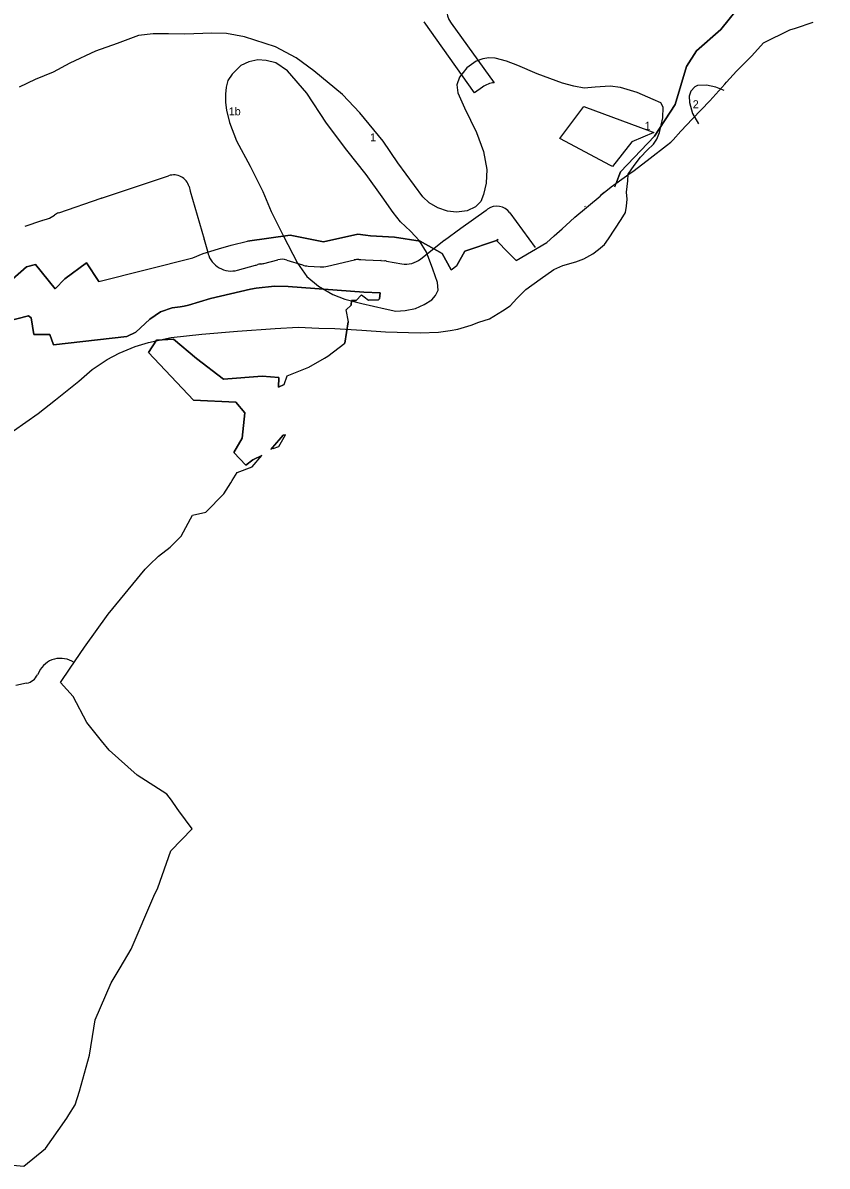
# Model space of a CAD drawing. Extents: x -445049 to -430649, y -1142304 to -1129816.
# Drawn here: x -443678 to -442673, y -1134562 to -1133134 of the extents above; entities that cross this region are included whole.
import ezdxf

# ---------------------------------------------------------------- set-up
doc = ezdxf.new("R2010")
doc.units = 0
for name, color, linetype in [('Vrstva 23', 7, 'Continuous'), ('Vrstva 51', 7, 'Continuous'), ('Vrstva 7', 7, 'Continuous'), ('Vrstva 8', 7, 'Continuous'), ('Vrstva 9', 7, 'Continuous')]:
    doc.layers.add(name, color=color, linetype=linetype)

msp = doc.modelspace()

# ---------------------------------------------------------------- linework, layer by layer
at = {"layer": 'Vrstva 23'}
for p, q in [((-443143, -1133133.8), (-443089, -1133208.5)), ((-443508.6, -1133328.8), (-443496, -1133324.6)), ((-443580.1, -1133352.5), (-443508.6, -1133328.8)), ((-443470.4, -1133338.2), (-443468.9, -1133343.7)), ((-443633.3, -1133370.9), (-443580.4, -1133352.6)), ((-443468.9, -1133343.8), (-443451.7, -1133404)), ((-443098.9, -1133367.5), (-443097.4, -1133366.4)), ((-443675.3, -1133387.8), (-443654.3, -1133380.7)), ((-443654.3, -1133380.7), (-443647.3, -1133378.3)), ((-443069.5, -1133370.9), (-443037.8, -1133414.4)), ((-443451.6, -1133404.2), (-443446.8, -1133421.6)), ((-443180.9, -1133428.5), (-443152.1, -1133405.6)), ((-443409.9, -1133442.6), (-443387.3, -1133436.4)), ((-443376.9, -1133434.1), (-443359.4, -1133429.6)), ((-443348.4, -1133429.9), (-443328.7, -1133436.1)), ((-443321.6, -1133437.4), (-443306.4, -1133438.4)), ((-443297.6, -1133437.7), (-443263.9, -1133429.8)), ((-443258.4, -1133429.3), (-443255.8, -1133429.4)), ((-443255.7, -1133429.4), (-443250, -1133429.7)), ((-443250, -1133429.7), (-443230.8, -1133430.7)), ((-443230.6, -1133430.7), (-443225.9, -1133431)), ((-443223.8, -1133431.2), (-443204.7, -1133434.5)), ((-443658, -1133944.3), (-443659.9, -1133948.1)), ((-443673.5, -1133958.7), (-443687, -1133961.7))]:
    msp.add_line(p, q, dxfattribs=at)
for points in [[(-443103.8, -1133213.9), (-443113.6, -1133220.9), (-443176.6, -1133132.3)], [(-443151.3, -1133405), (-443130.7, -1133390.3), (-443099, -1133367.6)]]:
    msp.add_lwpolyline(points, dxfattribs=at)
for centre, radius, start, end in [((-443118.7, -1133116.3), 30, 138.9795, 215.8663), ((-443086.4, -1133238.3), 30, 95.036, 125.4139), ((-443489.7, -1133343.6), 20, 15.6761, 108.4331), ((-443518.1, -1133300.3), 30, 288.3161, 288.4331), ((-443573.8, -1133371.5), 20, 108.3161, 109.0994), ((-443440, -1133335.6), 30, 195.6761, 195.9557), ((-443116.4, -1133343.2), 30, 305.6204, 305.8262), ((-443085.7, -1133382.7), 20, 36.0604, 125.8262), ((-443663.9, -1133352.3), 30, 288.6899, 288.7113), ((-443656.9, -1133349.9), 30, 288.7113, 307.1241), ((-443626.7, -1133389.8), 20, 109.0994, 127.1241), ((-443470.9, -1133409.5), 20, 15.2701, 15.9557), ((-443139.6, -1133421.3), 20, 125.615, 128.3723), ((-443417.9, -1133413.7), 30, 195.2701, 285.3949), ((-443395.3, -1133407.5), 30, 285.3949, 289.0956), ((-443378.9, -1133454.7), 20, 96.1778, 109.0956), ((-443384.3, -1133405), 30, 276.1778, 284.3857), ((-443354.4, -1133449), 20, 72.539, 104.3857), ((-443319.7, -1133407.5), 30, 252.539, 266.3185), ((-443304.4, -1133408.5), 30, 266.3185, 283.2162), ((-443259.4, -1133449.3), 20, 87.2484, 103.2162), ((-443256.8, -1133449.4), 20, 87.0859, 87.2484), ((-443248.5, -1133399.7), 30, 267.0859, 267.1026), ((-443231.8, -1133450.6), 20, 86.42, 87.1026), ((-443227.2, -1133450.9), 20, 80.1563, 86.42), ((-443199.6, -1133405), 30, 260.1563, 308.3723), ((-443631.1, -1133957.6), 30, 55.8038, 153.678), ((-443677.8, -1133939.2), 20, 282.5288, 333.678)]:
    msp.add_arc(centre, radius, start, end, dxfattribs=at)
at = {"layer": 'Vrstva 51'}
for points in [[(-442922.1, -1133330.9), (-442921.5, -1133322.5), (-442914.1, -1133311.8), (-442906.4, -1133301.6), (-442897.7, -1133292.6), (-442889.8, -1133285.1), (-442885.8, -1133278.9), (-442882.5, -1133270.6), (-442878.4, -1133252.1), (-442877.8, -1133239), (-442880.9, -1133233.7), (-442890.2, -1133229.2), (-442910.4, -1133220.7), (-442931.1, -1133214.2), (-442944.1, -1133212.8), (-442962.7, -1133214.1), (-442976.7, -1133215), (-442989.6, -1133212.5), (-443003.6, -1133209.1), (-443035.5, -1133197.4), (-443059.4, -1133186.8), (-443073.6, -1133181.5), (-443088, -1133177.7), (-443096, -1133177.1), (-443103.5, -1133178.5), (-443111.8, -1133181.3), (-443123.2, -1133189.7), (-443132.6, -1133201.3), (-443135.6, -1133211.1), (-443134.4, -1133220.9), (-443126.2, -1133239.6), (-443111.2, -1133270.4), (-443102.5, -1133294.2), (-443098.5, -1133316.9), (-443099.3, -1133333.8), (-443102.4, -1133348.2), (-443105.7, -1133356.8), (-443112.4, -1133363.6), (-443122.8, -1133368.6), (-443136, -1133370.3), (-443147.5, -1133368.7), (-443159.5, -1133364.7), (-443170.2, -1133358.5), (-443178.1, -1133351), (-443209.6, -1133308.5), (-443227.7, -1133281.3), (-443257, -1133246), (-443278.8, -1133223.1), (-443314.4, -1133193.4), (-443336.7, -1133177.1), (-443362.6, -1133163.6), (-443401, -1133151.1), (-443423.8, -1133146.7), (-443441.9, -1133146.4), (-443475.6, -1133147.8), (-443496, -1133147.4), (-443515.4, -1133147.2), (-443533.6, -1133149.5), (-443560.5, -1133159.4), (-443587.4, -1133168.8), (-443619.3, -1133184), (-443640.2, -1133195.2), (-443663, -1133204.5), (-443682.9, -1133214)], [(-442801.5, -1133218.1), (-442811.9, -1133213.9), (-442823.7, -1133211.4), (-442834.9, -1133211.8), (-442838.5, -1133213.4), (-442843.5, -1133218.8), (-442845.6, -1133225.2), (-442845, -1133233), (-442841.4, -1133246.7), (-442833.9, -1133259.6)], [(-443254.6, -1133517.4), (-443224.9, -1133519.7), (-443181.8, -1133520.9), (-443158.6, -1133520), (-443144, -1133518), (-443134.6, -1133516.2), (-443117.8, -1133511.5), (-443108.5, -1133507.4), (-443095.1, -1133503.4), (-443078.6, -1133493.4), (-443069.2, -1133487.2), (-443060.8, -1133477.8), (-443049.6, -1133466.7), (-443031.6, -1133453.8), (-443014.5, -1133441.9), (-443003.3, -1133436.6), (-442987.2, -1133432), (-442976.9, -1133428.6), (-442965.6, -1133422.1), (-442958.7, -1133416.8), (-442951.3, -1133410.5), (-442946.1, -1133403.5), (-442930.4, -1133379.3), (-442925.1, -1133370.4), (-442923.8, -1133362.8), (-442923.1, -1133354), (-442923.6, -1133345.1), (-442922.1, -1133330.9)], [(-443690, -1133643.2), (-443659.1, -1133621.8), (-443637.2, -1133604.4), (-443608.2, -1133581.4), (-443591.7, -1133566.7), (-443572.7, -1133554.2), (-443557.7, -1133546.1), (-443538, -1133537.8), (-443521.2, -1133532.9), (-443493, -1133526.8), (-443454.6, -1133522.5), (-443410, -1133518.6), (-443363, -1133515.5), (-443334.1, -1133514), (-443308.4, -1133514.9), (-443288.4, -1133515.4), (-443254.6, -1133517.4)]]:
    msp.add_lwpolyline(points, dxfattribs=at)
msp.add_lwpolyline([(-443173.7, -1133420), (-443182.3, -1133405.8), (-443193.7, -1133393.8), (-443206.3, -1133382), (-443215.5, -1133370.5), (-443229, -1133351), (-443249.3, -1133322.9), (-443273.2, -1133292.5), (-443298.5, -1133259), (-443323.4, -1133221.3), (-443347.5, -1133193.6), (-443362.2, -1133183.7), (-443374.3, -1133180.5), (-443384.7, -1133179.7), (-443395.7, -1133182.3), (-443405.6, -1133187), (-443416.5, -1133197.7), (-443422.1, -1133205.8), (-443423.9, -1133214.1), (-443424.9, -1133222.5), (-443424.9, -1133232.9), (-443423.7, -1133242.7), (-443419.9, -1133258), (-443411.2, -1133281), (-443393.9, -1133312.8), (-443378.2, -1133344.4), (-443367.7, -1133369.1), (-443353, -1133399.1), (-443335.1, -1133434), (-443323.3, -1133450.4), (-443308.8, -1133462.6), (-443290.6, -1133472.9), (-443275.7, -1133479), (-443254.5, -1133484.1), (-443225.3, -1133490.9), (-443212, -1133493.8), (-443200.4, -1133493.1), (-443187.5, -1133490.3), (-443176.7, -1133485.3), (-443167, -1133479.8), (-443162.4, -1133474.4), (-443159.2, -1133467.7), (-443160, -1133458), (-443165.7, -1133441.4)], close=True, dxfattribs=at)
at = {"layer": 'Vrstva 7'}
for points in [[(-443712.5, -1133472.1), (-443673.7, -1133438.5), (-443662.5, -1133435.5), (-443638, -1133466.1), (-443625.9, -1133453.6), (-443598.5, -1133433.4), (-443583.4, -1133456.8), (-443465.7, -1133427.3), (-443452.8, -1133421.7), (-443433.7, -1133416), (-443418, -1133411.2), (-443397.6, -1133406.4), (-443344.3, -1133398.7), (-443302.5, -1133407.1), (-443259.6, -1133397.6), (-443249.9, -1133398.8), (-443243.6, -1133399.5), (-443213.8, -1133401.2), (-443181.5, -1133406.4), (-443154.3, -1133421.9), (-443143, -1133442.1), (-443135.6, -1133436.7), (-443125.8, -1133419), (-443086.4, -1133405.7), (-443084.2, -1133404.2), (-443086.4, -1133405.7), (-443071.4, -1133421), (-443061.5, -1133430.7), (-443023.3, -1133407.9), (-443019.2, -1133404.3), (-443014, -1133399.8), (-443004.2, -1133390.8), (-442994.3, -1133381.9), (-442988.4, -1133376.5), (-442956.8, -1133350), (-442951.6, -1133345.7), (-442943, -1133338.4), (-442923.8, -1133324.8), (-442921.9, -1133323.4), (-442914.2, -1133317.9), (-442894.3, -1133302.8), (-442873.8, -1133286.9), (-442868.2, -1133282.6), (-442865.4, -1133279.6), (-442855.8, -1133269.1), (-442841.2, -1133253.6), (-442819.5, -1133231), (-442812, -1133222.7), (-442800.9, -1133210.2), (-442798.6, -1133207.7), (-442786.1, -1133194), (-442767.1, -1133174.9), (-442752.3, -1133158.7), (-442719.4, -1133142.5), (-442712.7, -1133140.2), (-442690.5, -1133132.6)], [(-442951.6, -1133345.7), (-442943, -1133338.4), (-442923.8, -1133324.8), (-442921.9, -1133323.4), (-442914.2, -1133317.9), (-442894.3, -1133302.8), (-442873.8, -1133286.9), (-442868.2, -1133282.6), (-442865.4, -1133279.6), (-442855.8, -1133269.1), (-442841.2, -1133253.6), (-442819.5, -1133231), (-442812, -1133222.7), (-442800.9, -1133210.2), (-442798.6, -1133207.7), (-442786.1, -1133194), (-442767.1, -1133174.9), (-442752.3, -1133158.7), (-442719.4, -1133142.5), (-442712.7, -1133140.2), (-442690.5, -1133132.6)], [(-442917.1, -1133282.1), (-442941.2, -1133313.1), (-442943.6, -1133311.8), (-443006.9, -1133278), (-442977.1, -1133238.1), (-442894.9, -1133268.6), (-442889.4, -1133270.7), (-442917.1, -1133282.1)], [(-442894.9, -1133268.6), (-442889.4, -1133270.7), (-442917.1, -1133282.1), (-442941.2, -1133313.1), (-442943.6, -1133311.8), (-443006.9, -1133278), (-442977.1, -1133238.1), (-442894.9, -1133268.6)], [(-443006.9, -1133278), (-442977.1, -1133238.1), (-442894.9, -1133268.6), (-442889.4, -1133270.7), (-442917.1, -1133282.1), (-442941.2, -1133313.1), (-442943.6, -1133311.8), (-443006.9, -1133278)], [(-443006.9, -1133278), (-442977.1, -1133238.1), (-442894.9, -1133268.6), (-442889.4, -1133270.7), (-442917.1, -1133282.1), (-442941.2, -1133313.1), (-442943.6, -1133311.8), (-443006.9, -1133278)], [(-443712.5, -1133472.1), (-443673.7, -1133438.5), (-443662.5, -1133435.5), (-443638, -1133466.1), (-443625.9, -1133453.6), (-443598.5, -1133433.4), (-443583.4, -1133456.8), (-443465.7, -1133427.3), (-443452.8, -1133421.7), (-443433.7, -1133416), (-443418, -1133411.2), (-443397.6, -1133406.4), (-443344.3, -1133398.7), (-443302.5, -1133407.1), (-443259.6, -1133397.6), (-443249.9, -1133398.8), (-443243.6, -1133399.5), (-443213.8, -1133401.2), (-443181.5, -1133406.4), (-443154.3, -1133421.9), (-443143, -1133442.1), (-443135.6, -1133436.7), (-443125.8, -1133419), (-443086.4, -1133405.7), (-443084.2, -1133404.2), (-443086.4, -1133405.7), (-443071.4, -1133421), (-443061.5, -1133430.7), (-443023.3, -1133407.9), (-443019.2, -1133404.3), (-443014, -1133399.8), (-443004.2, -1133390.8), (-442994.3, -1133381.9), (-442988.4, -1133376.5), (-442956.8, -1133350)], [(-442951.6, -1133345.7), (-442956.5, -1133349.8)], [(-442975.2, -1133362.9), (-442976.1, -1133363.5)], [(-443712.5, -1133472.1), (-443673.7, -1133438.5), (-443662.5, -1133435.5), (-443638, -1133466.1), (-443625.9, -1133453.6), (-443598.5, -1133433.4), (-443583.4, -1133456.8), (-443465.7, -1133427.3), (-443452.8, -1133421.7), (-443433.7, -1133416), (-443418, -1133411.2), (-443397.6, -1133406.4), (-443344.3, -1133398.7), (-443302.5, -1133407.1), (-443259.6, -1133397.6), (-443249.9, -1133398.8), (-443243.6, -1133399.5), (-443213.8, -1133401.2), (-443181.5, -1133406.4), (-443154.3, -1133421.9), (-443143, -1133442.1), (-443135.6, -1133436.7), (-443125.8, -1133419), (-443086.4, -1133405.7), (-443084.2, -1133404.2)], [(-443583.4, -1133456.8), (-443465.7, -1133427.3), (-443452.8, -1133421.7), (-443433.7, -1133416), (-443418, -1133411.2), (-443397.6, -1133406.4)], [(-443143, -1133442.1), (-443154.3, -1133421.9), (-443181.5, -1133406.4), (-443213.8, -1133401.2), (-443243.6, -1133399.5), (-443249.9, -1133398.8), (-443259.6, -1133397.6), (-443302.5, -1133407.1), (-443344.3, -1133398.7), (-443397.6, -1133406.4)], [(-443084.2, -1133404.2), (-443086.4, -1133405.7), (-443125.8, -1133419), (-443135.6, -1133436.8)], [(-443583.4, -1133456.8), (-443598.5, -1133433.4), (-443625.9, -1133453.6), (-443638, -1133466.1), (-443662.5, -1133435.5), (-443673.7, -1133438.5), (-443712.5, -1133472.1), (-443735.9, -1133482.8), (-443718.8, -1133511.9), (-443671.1, -1133499.8), (-443668, -1133502.3), (-443664.3, -1133522.9), (-443644.5, -1133522.8), (-443640, -1133535.8), (-443548.3, -1133525.6)], [(-443737, -1134556.5), (-443676.9, -1134562.1), (-443649.8, -1134540.2), (-443633.9, -1134517.4), (-443623.1, -1134502.1), (-443620.7, -1134498.1), (-443613, -1134485.6), (-443607.6, -1134468.5), (-443594.8, -1134423.4), (-443589.3, -1134389.5), (-443587.7, -1134379.4), (-443567.8, -1134333.2), (-443556.7, -1134314.5), (-443542.7, -1134290.9), (-443514.7, -1134224.7), (-443509.6, -1134214.4), (-443493.3, -1134168), (-443466.4, -1134140.8), (-443483.2, -1134118.2), (-443485.3, -1134115.3), (-443492.5, -1134104.8), (-443498.3, -1134097.4), (-443535.5, -1134073.4), (-443570.5, -1134042.3), (-443579.9, -1134030.6), (-443598.2, -1134007.9), (-443615.3, -1133975.2), (-443631.1, -1133957.6), (-443619, -1133939.8), (-443601.3, -1133913.7), (-443571.4, -1133872.6), (-443525.4, -1133816.1), (-443519.9, -1133810.9), (-443508.5, -1133799.8), (-443494.1, -1133788.5), (-443480.2, -1133775), (-443468.6, -1133753.3), (-443466.2, -1133748.9), (-443449.4, -1133745.1), (-443427.1, -1133722.1), (-443418.4, -1133708.5), (-443416.5, -1133705.4), (-443410.3, -1133695.4), (-443391.7, -1133688.2), (-443379.6, -1133674.2), (-443390.8, -1133679.5), (-443399.5, -1133686.1), (-443414.5, -1133670.6), (-443404, -1133652.5), (-443400.8, -1133620.8), (-443412.2, -1133607.4), (-443465, -1133605), (-443521.1, -1133545.4), (-443511.2, -1133529.9), (-443489.9, -1133528.6), (-443461.2, -1133553), (-443427.5, -1133578.8), (-443379, -1133575.1), (-443358.3, -1133576.6), (-443358.5, -1133588.7), (-443351.8, -1133585.6), (-443347.8, -1133574.5), (-443320.6, -1133563.8), (-443301.3, -1133552.4), (-443297.2, -1133549.9), (-443275.6, -1133533.6), (-443271.6, -1133507.3), (-443271.3, -1133507.1), (-443274.1, -1133492.3), (-443267.8, -1133486.2), (-443267.3, -1133480.4), (-443261.8, -1133480.3), (-443254.8, -1133473.4), (-443251.5, -1133475.9), (-443246.4, -1133479.9), (-443233.7, -1133479.6), (-443232.3, -1133478.6), (-443231.6, -1133471.1), (-443252.2, -1133470.2), (-443346.6, -1133462.9), (-443363.8, -1133462.4), (-443386.4, -1133465.1), (-443393.6, -1133466.3), (-443443.7, -1133477.9), (-443471.1, -1133486.5), (-443476.7, -1133487.4), (-443481.5, -1133488.2), (-443491.5, -1133489.8), (-443506.2, -1133494.5), (-443519.4, -1133503.8), (-443536.8, -1133520), (-443548.3, -1133525.6), (-443640, -1133535.8), (-443644.5, -1133522.8), (-443664.3, -1133522.9), (-443668, -1133502.3), (-443671.1, -1133499.8), (-443718.8, -1133511.9)], [(-443737, -1134556.5), (-443676.9, -1134562.1), (-443649.8, -1134540.2), (-443633.9, -1134517.4), (-443623.1, -1134502.1), (-443620.7, -1134498.1), (-443613, -1134485.6), (-443607.6, -1134468.5), (-443594.8, -1134423.4), (-443589.3, -1134389.5), (-443587.7, -1134379.4), (-443567.8, -1134333.2), (-443556.7, -1134314.5), (-443542.7, -1134290.9), (-443514.7, -1134224.7), (-443509.6, -1134214.4), (-443493.3, -1134168), (-443466.4, -1134140.8), (-443483.2, -1134118.2), (-443485.3, -1134115.3), (-443492.5, -1134104.8), (-443498.3, -1134097.4), (-443535.5, -1134073.4), (-443570.5, -1134042.3), (-443579.9, -1134030.6), (-443598.2, -1134007.9), (-443615.3, -1133975.2), (-443631.1, -1133957.6), (-443619, -1133939.8), (-443601.3, -1133913.7), (-443571.4, -1133872.6), (-443525.4, -1133816.1), (-443519.9, -1133810.9), (-443508.5, -1133799.8), (-443494.1, -1133788.5), (-443480.2, -1133775), (-443468.6, -1133753.3), (-443466.2, -1133748.9), (-443449.4, -1133745.1), (-443427.1, -1133722.1), (-443418.4, -1133708.5), (-443416.5, -1133705.4), (-443410.3, -1133695.4), (-443391.7, -1133688.2), (-443379.6, -1133674.2), (-443390.8, -1133679.5), (-443399.5, -1133686.1), (-443414.5, -1133670.6), (-443404, -1133652.5), (-443400.8, -1133620.8), (-443412.2, -1133607.4), (-443465, -1133605), (-443521.1, -1133545.4), (-443511.2, -1133529.9), (-443489.9, -1133528.6), (-443461.2, -1133553), (-443427.5, -1133578.8), (-443379, -1133575.1), (-443358.3, -1133576.6), (-443358.5, -1133588.7), (-443351.8, -1133585.6), (-443347.8, -1133574.5), (-443320.6, -1133563.8), (-443301.3, -1133552.4), (-443297.2, -1133549.9), (-443275.6, -1133533.6), (-443271.6, -1133507.3), (-443271.3, -1133507.1), (-443274.1, -1133492.3), (-443267.8, -1133486.2), (-443267.3, -1133480.4), (-443261.8, -1133480.3), (-443254.8, -1133473.4), (-443251.5, -1133475.9), (-443246.4, -1133479.9), (-443233.7, -1133479.6), (-443232.3, -1133478.6), (-443231.6, -1133471.1), (-443252.2, -1133470.2), (-443346.6, -1133462.9), (-443363.8, -1133462.4), (-443386.4, -1133465.1), (-443393.6, -1133466.3), (-443443.7, -1133477.9), (-443471.1, -1133486.5), (-443476.7, -1133487.4), (-443481.5, -1133488.2), (-443491.5, -1133489.8), (-443506.2, -1133494.5), (-443519.4, -1133503.8), (-443536.8, -1133520), (-443548.3, -1133525.6), (-443640, -1133535.8), (-443644.5, -1133522.8), (-443664.3, -1133522.9), (-443668, -1133502.3), (-443671.1, -1133499.8), (-443718.8, -1133511.9)], [(-443737, -1134556.5), (-443676.9, -1134562.1), (-443649.8, -1134540.2), (-443633.9, -1134517.4), (-443623.1, -1134502.1), (-443620.7, -1134498.1), (-443613, -1134485.6), (-443607.6, -1134468.5), (-443594.8, -1134423.4), (-443589.3, -1134389.5), (-443587.7, -1134379.4), (-443567.8, -1134333.2), (-443556.7, -1134314.5), (-443542.7, -1134290.9), (-443514.7, -1134224.7), (-443509.6, -1134214.4), (-443493.3, -1134168), (-443466.4, -1134140.8), (-443483.2, -1134118.2), (-443485.3, -1134115.3), (-443492.5, -1134104.8), (-443498.3, -1134097.4), (-443535.5, -1134073.4), (-443570.5, -1134042.3), (-443579.9, -1134030.6), (-443598.2, -1134007.9), (-443615.3, -1133975.2), (-443631.1, -1133957.6), (-443619, -1133939.8), (-443601.3, -1133913.7), (-443571.4, -1133872.6), (-443525.4, -1133816.1), (-443519.9, -1133810.9), (-443508.5, -1133799.8), (-443494.1, -1133788.5), (-443480.2, -1133775), (-443468.6, -1133753.3), (-443466.2, -1133748.9), (-443449.4, -1133745.1), (-443427.1, -1133722.1), (-443418.4, -1133708.5), (-443416.5, -1133705.4), (-443410.3, -1133695.4), (-443391.7, -1133688.2), (-443379.6, -1133674.2), (-443390.8, -1133679.5), (-443399.5, -1133686.1), (-443414.5, -1133670.6), (-443404, -1133652.5), (-443400.8, -1133620.8), (-443412.2, -1133607.4), (-443465, -1133605), (-443521.1, -1133545.4), (-443511.2, -1133529.9), (-443489.9, -1133528.6), (-443461.2, -1133553), (-443427.5, -1133578.8), (-443379, -1133575.1), (-443358.3, -1133576.6), (-443358.5, -1133588.7), (-443351.8, -1133585.6), (-443347.8, -1133574.5), (-443320.6, -1133563.8), (-443301.3, -1133552.4), (-443297.2, -1133549.9), (-443275.6, -1133533.6), (-443271.6, -1133507.3), (-443271.3, -1133507.1), (-443274.1, -1133492.3), (-443267.8, -1133486.2), (-443267.3, -1133480.4), (-443261.8, -1133480.3), (-443254.8, -1133473.4), (-443251.5, -1133475.9), (-443246.4, -1133479.9), (-443233.7, -1133479.6), (-443232.3, -1133478.6), (-443231.6, -1133471.1), (-443252.2, -1133470.2), (-443346.6, -1133462.9), (-443363.8, -1133462.4), (-443386.4, -1133465.1), (-443393.6, -1133466.3), (-443443.7, -1133477.9), (-443471.1, -1133486.5), (-443476.7, -1133487.4), (-443481.5, -1133488.2), (-443491.5, -1133489.8), (-443506.2, -1133494.5), (-443519.4, -1133503.8), (-443536.8, -1133520), (-443548.3, -1133525.6), (-443640, -1133535.8), (-443644.5, -1133522.8), (-443664.3, -1133522.9), (-443668, -1133502.3), (-443671.1, -1133499.8), (-443718.8, -1133511.9)], [(-443548.3, -1133525.6), (-443536.8, -1133520), (-443519.4, -1133503.8), (-443506.2, -1133494.5), (-443491.5, -1133489.8), (-443481.5, -1133488.2), (-443476.7, -1133487.4), (-443471.1, -1133486.5), (-443443.7, -1133477.9), (-443393.6, -1133466.3), (-443386.4, -1133465.1)], [(-443386.4, -1133465.1), (-443363.8, -1133462.4), (-443346.6, -1133462.9), (-443252.2, -1133470.2), (-443231.6, -1133471.1), (-443232.3, -1133478.6), (-443233.7, -1133479.6), (-443246.7, -1133479.9)], [(-443261.8, -1133480.3), (-443267.3, -1133480.4), (-443267.8, -1133486.2)], [(-443271.2, -1133507), (-443271.6, -1133507.3), (-443275.6, -1133533.7)], [(-443351.8, -1133585.6), (-443358.5, -1133588.7), (-443358.3, -1133576.6), (-443379, -1133575.1), (-443427.5, -1133578.8), (-443461.2, -1133553), (-443489.9, -1133528.6), (-443511.2, -1133529.9), (-443521.1, -1133545.4), (-443465, -1133605), (-443412.2, -1133607.4), (-443400.8, -1133620.8), (-443404, -1133652.5), (-443414.5, -1133670.6), (-443399.5, -1133686.1), (-443390.8, -1133679.5), (-443379.5, -1133674.2)], [(-443368.4, -1133666.7), (-443352.8, -1133648.6), (-443349.9, -1133648.1)], [(-443366.6, -1133664.6), (-443365.3, -1133665.5), (-443358.3, -1133662.8), (-443350, -1133648.2), (-443352.8, -1133648.6), (-443366.6, -1133664.6)]]:
    msp.add_lwpolyline(points, dxfattribs=at)
msp.add_lwpolyline([(-442941.2, -1133313.1), (-442943.6, -1133311.8), (-443006.9, -1133278), (-442977.1, -1133238.1), (-442894.9, -1133268.6), (-442889.4, -1133270.7), (-442917.1, -1133282.1)], close=True, dxfattribs=at)
at = {"layer": 'Vrstva 8'}
msp.add_lwpolyline([(-442673, -1133032.7), (-442697.7, -1133030.5), (-442713.3, -1133033), (-442726.6, -1133035.1), (-442761.5, -1133060.8), (-442776.1, -1133104.8), (-442805.7, -1133141.9), (-442836.2, -1133168.5), (-442848.8, -1133188.3), (-442862.9, -1133235.4), (-442888.6, -1133275), (-442931.2, -1133319.7), (-442936.7, -1133334)], dxfattribs=at)
at = {"layer": 'Vrstva 9'}
msp.add_lwpolyline([(-442938.5, -1133338.6), (-442931.2, -1133319.7), (-442888.6, -1133275), (-442862.9, -1133235.4), (-442848.8, -1133188.3), (-442836.2, -1133168.5), (-442805.7, -1133141.9), (-442776.1, -1133104.8)], dxfattribs=at)

# ---------------------------------------------------------------- texts
at = {"layer": 'Vrstva 51'}
for s, p in [('1b', (-443420.8, -1133249.1)), ('2', (-442840.9, -1133240.3)), ('1', (-442901, -1133267.2)), ('1', (-443244.2, -1133281.6))]:
    msp.add_text(s, height=10, dxfattribs=at).set_placement(p)

doc.saveas('drawing.dxf')
